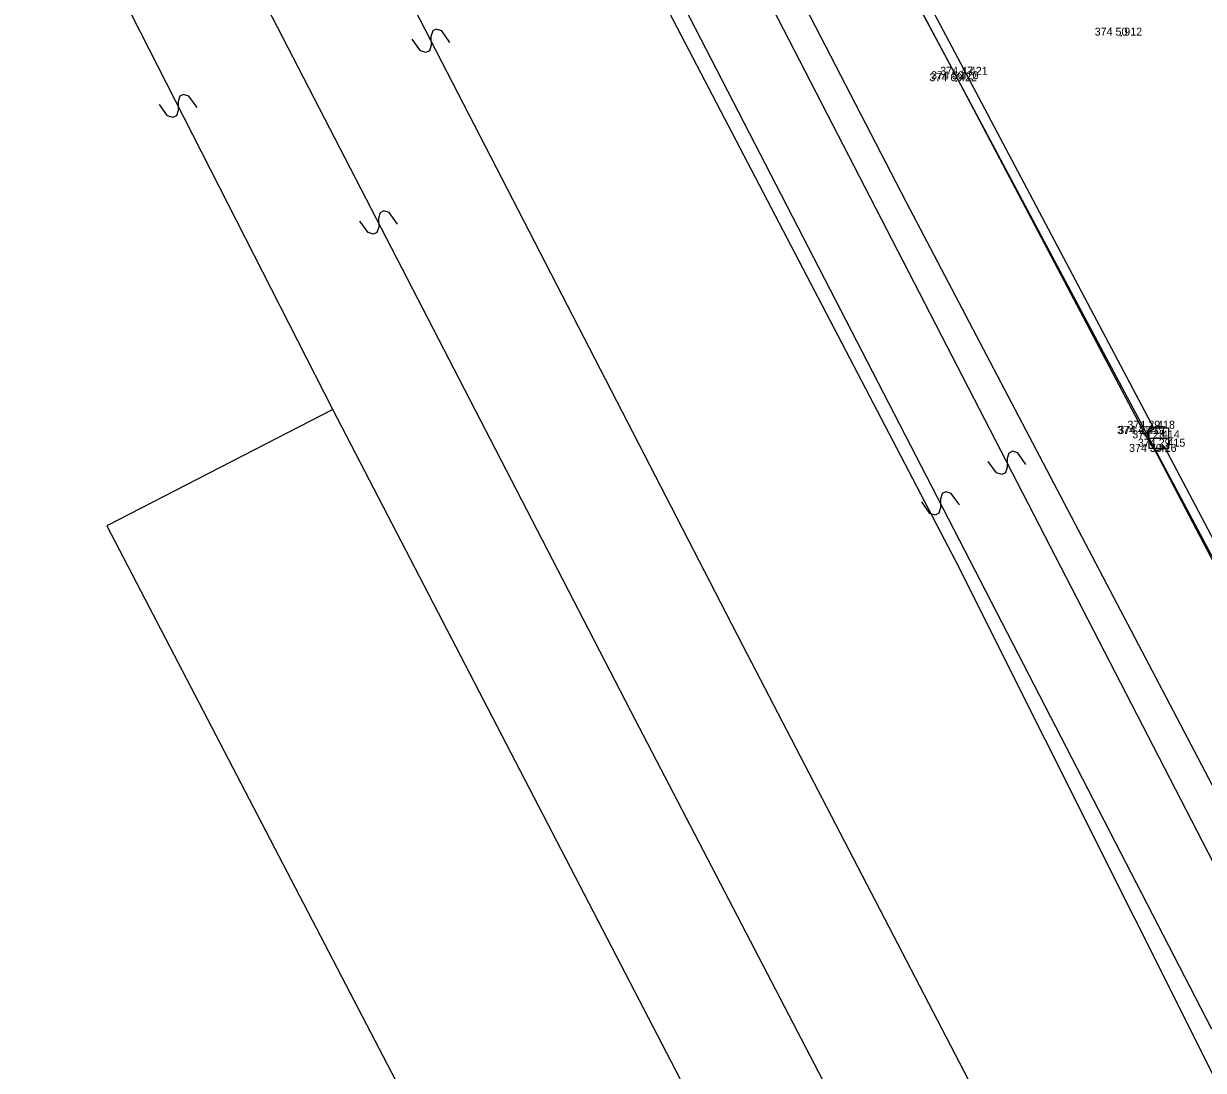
# Model space of a CAD drawing. Extents: x -601196 to -600262, y -1082523 to -1081922.
# Drawn here: x -600583.71 to -600554.22, y -1082174.68 to -1082148.5 of the extents above; entities that cross this region are included whole.
import ezdxf

# ---------------------------------------------------------------- set-up
doc = ezdxf.new("R2010")
doc.units = 0
for name, color, linetype in [('Vrstva 1', 7, 'Continuous'), ('Vrstva 10', 7, 'Continuous'), ('Vrstva 11', 7, 'Continuous'), ('Vrstva 2', 7, 'Continuous'), ('Vrstva 20', 7, 'Continuous'), ('Vrstva 27', 7, 'Continuous'), ('Vrstva 3', 7, 'Continuous'), ('Vrstva 47', 7, 'Continuous')]:
    doc.layers.add(name, color=color, linetype=linetype)

msp = doc.modelspace()

# ---------------------------------------------------------------- linework, layer by layer
at = {"layer": 'Vrstva 1'}
for p, q in [((-600556.27, -1082148.8), (-600556.27, -1082148.8)), ((-600560.4, -1082149.94), (-600560.4, -1082149.94)), ((-600560.36, -1082149.89), (-600560.36, -1082149.89)), ((-600560.13, -1082149.78), (-600560.13, -1082149.78)), ((-600555.71, -1082158.76), (-600555.71, -1082158.76)), ((-600555.68, -1082158.76), (-600555.68, -1082158.76)), ((-600555.45, -1082158.63), (-600555.45, -1082158.63)), ((-600555.33, -1082158.87), (-600555.33, -1082158.87)), ((-600555.19, -1082159.08), (-600555.19, -1082159.08)), ((-600555.41, -1082159.21), (-600555.41, -1082159.21))]:
    msp.add_line(p, q, dxfattribs=at)
at = {"layer": 'Vrstva 10'}
for p, q in [((-600560.36, -1082149.89), (-600567.11, -1082137.17)), ((-600555.68, -1082158.76), (-600560.36, -1082149.89)), ((-600555.41, -1082159.21), (-600555.68, -1082158.76)), ((-600553.48, -1082162.9), (-600555.41, -1082159.21))]:
    msp.add_line(p, q, dxfattribs=at)
at = {"layer": 'Vrstva 11'}
for p, q in [((-600560.13, -1082149.78), (-600566.89, -1082137.01)), ((-600555.45, -1082158.63), (-600560.13, -1082149.78)), ((-600555.68, -1082158.76), (-600555.45, -1082158.63)), ((-600555.19, -1082159.08), (-600555.41, -1082159.21)), ((-600553.23, -1082162.81), (-600555.19, -1082159.08))]:
    msp.add_line(p, q, dxfattribs=at)
at = {"layer": 'Vrstva 20'}
for p, q in [((-600556.28, -1082148.8), (-600556.26, -1082148.8)), ((-600556.27, -1082148.785), (-600556.27, -1082148.8)), ((-600556.27, -1082148.815), (-600556.27, -1082148.8)), ((-600560.41, -1082149.94), (-600560.39, -1082149.94)), ((-600560.4, -1082149.925), (-600560.4, -1082149.94)), ((-600560.4, -1082149.955), (-600560.4, -1082149.94)), ((-600555.72, -1082158.76), (-600555.7, -1082158.76)), ((-600555.71, -1082158.745), (-600555.71, -1082158.76)), ((-600555.71, -1082158.775), (-600555.71, -1082158.76))]:
    msp.add_line(p, q, dxfattribs=at)
at = {"layer": 'Vrstva 27'}
msp.add_line((-600555.58, -1082158.87), (-600555.08, -1082158.87), dxfattribs=at)
msp.add_lwpolyline([(-600555.58, -1082159.12), (-600555.08, -1082159.12), (-600555.08, -1082158.62), (-600555.58, -1082158.62)], close=True, dxfattribs=at)
at = {"layer": 'Vrstva 47'}
for p, q in [((-600581.31, -1082133.82), (-600565.74, -1082164.04)), ((-600561.65, -1082152.96), (-600571.28, -1082134.28)), ((-600560.4, -1082161.96), (-600571.36, -1082140.95)), ((-600568.53, -1082165.69), (-600581.14, -1082141.26)), ((-600575.98, -1082158.15), (-600583.71, -1082142.97)), ((-600563.02, -1082144.88), (-600549.06, -1082171.12)), ((-600552.31, -1082172.71), (-600565.94, -1082146.26)), ((-600554.01, -1082173.65), (-600567.57, -1082147.35)), ((-600573.483, -1082148.683), (-600573.526, -1082148.818)), ((-600573.394, -1082148.637), (-600573.483, -1082148.683)), ((-600573.259, -1082148.68), (-600573.394, -1082148.637)), ((-600573.054, -1082148.969), (-600573.259, -1082148.68)), ((-600573.79, -1082149.179), (-600573.995, -1082148.89)), ((-600573.523, -1082149.041), (-600573.566, -1082149.176)), ((-600573.526, -1082148.818), (-600573.523, -1082149.041)), ((-600573.655, -1082149.222), (-600573.79, -1082149.179)), ((-600573.566, -1082149.176), (-600573.655, -1082149.222)), ((-600580.111, -1082150.807), (-600580.314, -1082150.518)), ((-600579.802, -1082150.313), (-600579.845, -1082150.448)), ((-600579.845, -1082150.448), (-600579.844, -1082150.671)), ((-600579.712, -1082150.268), (-600579.802, -1082150.313)), ((-600579.578, -1082150.312), (-600579.712, -1082150.268)), ((-600579.375, -1082150.601), (-600579.578, -1082150.312)), ((-600579.977, -1082150.851), (-600580.111, -1082150.807)), ((-600579.887, -1082150.806), (-600579.977, -1082150.851)), ((-600579.844, -1082150.671), (-600579.887, -1082150.806)), ((-600574.704, -1082153.182), (-600574.793, -1082153.228)), ((-600574.569, -1082153.225), (-600574.704, -1082153.182)), ((-600547.75, -1082179.45), (-600561.65, -1082152.96)), ((-600575.1, -1082153.724), (-600575.305, -1082153.436)), ((-600574.793, -1082153.228), (-600574.836, -1082153.363)), ((-600574.836, -1082153.363), (-600574.833, -1082153.586)), ((-600574.364, -1082153.513), (-600574.569, -1082153.225)), ((-600574.965, -1082153.767), (-600575.1, -1082153.724)), ((-600574.876, -1082153.721), (-600574.965, -1082153.767)), ((-600574.833, -1082153.586), (-600574.876, -1082153.721)), ((-600575.98, -1082158.15), (-600581.63, -1082161.06)), ((-600560.94, -1082187.13), (-600575.98, -1082158.15)), ((-600559.083, -1082159.238), (-600559.126, -1082159.373)), ((-600559.126, -1082159.373), (-600559.123, -1082159.596)), ((-600558.994, -1082159.192), (-600559.083, -1082159.238)), ((-600558.859, -1082159.235), (-600558.994, -1082159.192)), ((-600558.654, -1082159.524), (-600558.859, -1082159.235)), ((-600559.39, -1082159.734), (-600559.595, -1082159.446)), ((-600559.123, -1082159.596), (-600559.166, -1082159.731)), ((-600559.255, -1082159.777), (-600559.39, -1082159.734)), ((-600559.166, -1082159.731), (-600559.255, -1082159.777)), ((-600560.748, -1082160.253), (-600560.791, -1082160.388)), ((-600560.659, -1082160.207), (-600560.748, -1082160.253)), ((-600560.524, -1082160.25), (-600560.659, -1082160.207)), ((-600560.319, -1082160.538), (-600560.524, -1082160.25)), ((-600561.055, -1082160.749), (-600561.26, -1082160.461)), ((-600560.791, -1082160.388), (-600560.788, -1082160.611)), ((-600560.92, -1082160.792), (-600561.055, -1082160.749)), ((-600560.831, -1082160.746), (-600560.92, -1082160.792)), ((-600560.788, -1082160.611), (-600560.831, -1082160.746)), ((-600581.63, -1082161.06), (-600566.52, -1082190.08)), ((-600550.85, -1082181.01), (-600560.4, -1082161.96)), ((-600565.74, -1082164.04), (-600555.66, -1082183.44)), ((-600558.55, -1082184.89), (-600568.53, -1082165.69))]:
    msp.add_line(p, q, dxfattribs=at)

# ---------------------------------------------------------------- texts
at = {"layer": 'Vrstva 2'}
for s, p in [(' 912', (-600556.27, -1082148.8)), (' 421', (-600560.13, -1082149.78)), (' 422', (-600560.4, -1082149.94)), (' 420', (-600560.36, -1082149.89)), (' 418', (-600555.45, -1082158.63)), (' 419', (-600555.71, -1082158.76)), (' 417', (-600555.68, -1082158.76)), (' 414', (-600555.33, -1082158.87)), (' 416', (-600555.41, -1082159.21)), (' 415', (-600555.19, -1082159.08))]:
    msp.add_text(s, height=0.2, dxfattribs=at).set_placement(p)
at = {"layer": 'Vrstva 3'}
for s, p in [('374 50 ', (-600556.936, -1082148.8)), ('374 47 ', (-600560.796, -1082149.78)), ('374 60 ', (-600561.066, -1082149.94)), ('374 50 ', (-600561.026, -1082149.89)), ('374 29 ', (-600556.116, -1082158.63)), ('374 41 ', (-600556.376, -1082158.76)), ('374 27 ', (-600556.346, -1082158.76)), ('374 28 ', (-600555.996, -1082158.87)), ('374 30 ', (-600556.076, -1082159.21)), ('374 29 ', (-600555.856, -1082159.08))]:
    msp.add_text(s, height=0.2, dxfattribs=at).set_placement(p)

doc.saveas('drawing.dxf')
